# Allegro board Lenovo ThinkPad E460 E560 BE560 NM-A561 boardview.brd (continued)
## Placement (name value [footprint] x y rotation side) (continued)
RC435  10K_0402_5%  [R_0402]  119.17 97.07 0 top
RD1  1.8K_0402_1%  [R_0402]  58.98 36.69 90 top
RD2  2_0402_1%  [R_0402]  58.86 39.49 270 top
RD3  1.8K_0402_1%  [R_0402]  59.87 37.6 270 top
RD4  24.9_0402_1%  [R_0402]  57.08 38.57 90 top
RD9  1.8K_0402_1%  [R_0402]  101.53 24.73 90 top
RD10  2_0402_1%  [R_0402]  103.31 25.64 270 top
RD11  1.8K_0402_1%  [R_0402]  102.42 25.64 270 top
RD12  24.9_0402_1%  [R_0402]  105.09 25.64 270 top
RD15  1.8K_0402_1%  [R_0402]  58.27 49.95 90 top
RD16  1.8K_0402_1%  [R_0402]  59.15 50.86 270 top
RD17  2_0402_1%  [R_0402]  58.27 52.67 270 top
RD18  24.9_0402_1%  [R_0402]  56.5 51.75 90 top
RD19  10K_0402_5%  [R_0402]  121.6 48.48 90 top
RD21  470_0402_5%  [R_0402]  67.11 25.06 180 top
RD23  100K_0402_5%  [R_0402]  111.31 21.38 180 top
RD24  10K_0402_5%  [R_0402]  108.26 20.49 0 top
RD25  100K_0402_5%  [R_0402]  110.42 20.49 0 top
RE1  43_0402_5%  [R_0402]  197.92 38.83 90 top
RE2  10K_0402_5%  [R_0402]  201.29 61.13 90 top
RE3  100K_0402_1%  [R_0402]  183.2 55.62 180 top
RE4  100K_0402_5%  [R_0402]  207.17 51.42 270 top
RE5  4.7K_0402_5%  [R_0402]  183.19 49.39 180 top
RE6  4.7K_0402_5%  [R_0402]  183.2 46.47 180 top
RE7  18K_0402_1%  [R_0402]  183.2 56.51 180 top
RE8  10K_0402_5%  [R_0402]  203.88 57.27 0 top
RE9  10K_0402_5%  [R_0402]  208.21 133.44 180 top
RE15  100K_0402_5%  [R_0402]  204.92 51.04 180 top
RE31  10K_0402_5%  [R_0402]  188.78 40.83 270 top
RE32  10K_0402_5%  [R_0402]  187.89 40.83 270 top
RE33  10K_0402_5%  [R_0402]  191.22 37.52 270 top
RE38  10_0402_5%  [R_0402]  204.92 49.52 180 top
RE39  10K_0402_5%  [R_0402]  183.19 50.41 180 top
RE40  10K_0402_5%  [R_0402]  203 38.83 90 top
RE41  10K_0402_5%  [R_0402]  205.87 55.51 0 top
RE42  0_0402_5%  [R0402_SHORT]  204.12 55.51 0 top
RE43  0_0402_5%  [R0402_SHORT]  190.2 37.52 270 top
RE51  10K_0402_5%  [R_0402]  207.7 56.38 270 top
RE52  5.1K_0402_1%  [R_0402]  184.08 16.25 270 top
RE53  10K_0402_5%  [R_0402]  209.56 53.19 180 top
RG1  0_0402_5%  [R_0402]  198.33 65.04 0 top
RG4  100K_0402_5%  [R_0402]  197.21 70.98 270 top
RG5  10K_0402_5%  [R_0402]  206.3 72.1 90 top
RG6  10K_0402_5%  [R_0402]  204.27 72.1 90 top
RG7  0_0402_5%  [R_0402]  202.62 66.77 90 top
RG8  10K_0402_5%  [R_0402]  205.29 73.01 270 top
RL4  4.7K_0402_5%  [R_0402]  46.67 111.47 90 top
RL5  10K_0402_5%  [R_0402]  49.33 111.47 90 top
RL6  10K_0402_5%  [R_0402]  51.11 111.47 90 top
RL7  1K_0402_5%  [R_0402]  47.55 112.38 270 top
RL8  3.01K_0402_1%  [R_0402]  42.73 122.77 90 top
RL9  10K_0402_5%  [R_0402]  53.85 120.94 180 top
RL10  75_0805_5%  [R_0805]  22.54 124.14 0 bottom
RL11  75_0805_5%  [R_0805]  22.22 120.03 0 bottom
RL12  75_0805_5%  [R_0805]  22.7 114.52 0 bottom
RL13  75_0805_5%  [R_0805]  22.19 107.99 0 bottom
RL15  510_0402_1%  [R_0402]  18.34 124.2 270 bottom
RL16  510_0402_1%  [R_0402]  18.73 110.45 90 bottom
RL17  0_0402_5%  [R_0402]  53.85 120.05 180 top
RL18  0_0402_5%  [R0402_SHORT]  53.85 119.19 180 top
RL19  0_0603_5%  [R_0603]  60.88 122.59 180 top
RL20  0_0603_5%  [R0603_SHORT]  32 98.34 180 top
RL22  47K_0402_5%  [R_0402]  59.67 117.54 180 top
RL23  100K_0402_5%  [R_0402]  57.26 115.84 0 top
RL24  10K_0402_5%  [R_0402]  58.76 118.43 0 top
RL25  0_0402_5%  [R_0402]  58.17 114.95 180 top
RPC2  33_0804_8P4R_5%  [RP_0804_8P4R]  103.76 64.95 180 top
RPC9  10K_0804_8P4R_5%  [RP_0804_8P4R]  149.16 92.69 0 top
RPC15  10K_0804_8P4R_5%  [RP_0804_8P4R]  111.44 116.49 180 bottom
RPC18  10K_0804_8P4R_5%  [RP_0804_8P4R]  110.67 62.65 90 top
RPC22  10K_0804_8P4R_5%  [RP_0804_8P4R]  115.23 63.48 270 top
RPC23  33_0804_8P4R_5%  [RP_0804_8P4R]  124.53 121.01 270 bottom
RPC24  33_0804_8P4R_5%  [RP_0804_8P4R]  129.58 115.29 90 bottom
RPC200  10K_0804_8P4R_5%  [RP_0804_8P4R]  129.13 73.33 180 top
RPE1  10K_0804_8P4R_5%  [RP_0804_8P4R]  207.82 61.09 270 top
RPE2  10K_0804_8P4R_5%  [RP_0804_8P4R]  199.69 62.46 270 top
RPE3  10K_0804_8P4R_5%  [RP_0804_8P4R]  174.87 64.92 0 top
RPE4  100K_0804_8P4R_5%  [RP_0804_8P4R]  210.71 61.09 270 top
RPE5  2.2K_0804_8P4R_5%  [RP_0804_8P4R]  195.14 38.48 90 top
RT13  2.2K_0402_5%  [R_0402]  11.79 88.81 0 bottom
RT14  2.2K_0402_5%  [R_0402]  14.53 92.95 270 top
RT20  0_0402_5%  [R0402_SHORT]  13.68 88.59 270 top
RT21  75_0402_1%  [R_0402]  16.44 79.34 90 top
RT22  75_0402_1%  [R_0402]  16.44 81.62 90 top
RT23  75_0402_1%  [R_0402]  16.44 83.91 90 top
RT27  0_0402_5%  [R0402_SHORT]  16.69 92.18 270 top
RT28  0_0402_5%  [R0402_SHORT]  15.42 92.95 270 top
RT29  0_0402_5%  [R0402_SHORT]  11.79 87.92 0 bottom
RT34  0_0402_5%  [R0402_SHORT]  18.8 89.7 180 top
RT35  0_0402_5%  [R0402_SHORT]  19.46 94.43 180 top
RT36  2.2K_0402_5%  [R_0402]  24.69 94.43 270 top
RT37  2.2K_0402_5%  [R_0402]  12.71 87.03 180 bottom
RV4  0_0402_5%  [R_0402]  139.5 130.42 90 top
RV5  0_0402_5%  [R_0402]  138.61 130.42 90 top
RV6  1.69K_0402_1%  [R_0402]  144.53 140.91 180 top
RV7  1K_0402_5%  [R_0402]  151.69 151.58 180 top
RV8  1K_0402_5%  [R_0402]  142.77 140.2 90 top
RV9  10K_0402_5%  [R_0402]  129.57 94.43 180 bottom
RV10  1M_0402_5%  [R_0402]  165.74 131.1 180 bottom
RV11  10K_0402_5%  [R_0402]  152.91 116.47 0 top
RV13  10K_0402_5%  [R_0402]  153.83 118.25 180 top
RV14  10K_0402_5%  [R_0402]  152.01 116.7 270 top
RV15  10K_0402_5%  [R_0402]  156.39 112.56 180 top
RV16  0_0402_5%  [R_0402]  155.53 117.24 0 top
RV17  150_0402_1%  [R_0402]  158.93 129.63 90 bottom
RV18  40.2_0402_1%  [R_0402]  129.42 129.73 90 bottom
RV19  40.2_0402_1%  [R_0402]  133 129.73 90 bottom
RV20  100_0402_5%  [R_0402]  128.53 130.65 270 bottom
RV21  100_0402_5%  [R_0402]  134.83 130.65 270 bottom
RV22  40.2_0402_1%  [R_0402]  132.06 129.73 90 bottom
RV23  40.2_0402_1%  [R_0402]  135.72 129.76 90 bottom
RV24  100_0402_5%  [R_0402]  131.17 130.65 270 bottom
RV25  100_0402_5%  [R_0402]  136.61 130.67 270 bottom
RV26  243_0402_1%  [R_0402]  138.21 144.54 180 top
RV27  49.9_0402_1%  [R_0402]  167.32 154.62 180 bottom
RV28  10_0402_5%  [R_0402]  165.54 154.62 180 bottom
RV29  5.1K_0402_5%  [R_0402]  164.67 155.51 0 bottom
RV30  2.1K_0402_1%  [R_0402]  118.03 139.45 270 bottom
RV31  2.1K_0402_1%  [R_0402]  110.03 129.62 0 bottom
RV32  4.99K_0402_1%  [R_0402]  116.28 138.54 90 bottom
RV33  4.99K_0402_1%  [R_0402]  111.94 129.62 0 bottom
RV41  60.4_0402_1%  [R_0402]  115.06 137.63 0 top
RV42  60.4_0402_1%  [R_0402]  115.98 138.51 180 top
RV43  2.1K_0402_1%  [R_0402]  118.3 164.54 270 bottom
RV44  2.1K_0402_1%  [R_0402]  110.74 151.34 0 bottom
RV45  4.99K_0402_1%  [R_0402]  117.41 163.62 90 bottom
RV46  4.99K_0402_1%  [R_0402]  112.52 151.34 0 bottom
RV53  60.4_0402_1%  [R_0402]  115.01 160.13 0 top
RV54  60.4_0402_1%  [R_0402]  115.9 159.24 180 top
RV55  2.1K_0402_1%  [R_0402]  134.09 170.17 180 bottom
RV56  2.1K_0402_1%  [R_0402]  124.26 178.17 270 bottom
RV57  4.99K_0402_1%  [R_0402]  133.18 171.03 0 bottom
RV58  4.99K_0402_1%  [R_0402]  124.26 176.27 270 bottom
RV66  60.4_0402_1%  [R_0402]  133.15 173.14 270 top
RV67  60.4_0402_1%  [R_0402]  132.26 172.25 90 top
RV68  2.1K_0402_1%  [R_0402]  156.06 170.19 180 bottom
RV69  2.1K_0402_1%  [R_0402]  146.36 177.46 270 bottom
RV70  4.99K_0402_1%  [R_0402]  155.15 171.08 0 bottom
RV71  4.99K_0402_1%  [R_0402]  146.36 175.68 270 bottom
RV78  60.4_0402_1%  [R_0402]  155.15 173.14 270 top
RV79  60.4_0402_1%  [R_0402]  154.26 172.25 90 top
RV91  10K_0402_5%  [R_0402]  161.91 155.74 0 top
RV92  10K_0402_5%  [R_0402]  172.22 156.63 180 top
RV93  5.11K_0402_1%  [R_0402]  161.93 130.66 180 bottom
RV94  1K_0402_5%  [R_0402]  161.02 129.77 0 bottom
RV96  33_0402_5%  [R_0402]  166.12 156.83 90 top
RV97  33_0402_5%  [R_0402]  167.24 159.12 0 top
RV98  45.3K_0402_1%  [R_0402]  162.38 142.84 270 top
RV99  45.3K_0402_1%  [R_0402]  163.33 142.38 270 top
RV101  0_0402_5%  [R_0402]  161.5 148.27 180 top
RV102  47K_0402_5%  [R_0402]  163.76 127.85 90 top
RV103  10K_0402_5%  [R_0402]  163.76 129.76 90 top
RV104  47K_0402_5%  [R_0402]  164.65 130.67 270 top
RV105  2.2K_0402_5%  [R_0402]  164.65 128.77 270 top
RV106  8.45K_0402_1%  [R_0402]  158.04 129.63 90 bottom
RV107  10K_0402_1%  [R_0402]  159.49 129.83 0 top
RV108  4.99K_0402_1%  [R_0402]  151.69 141.77 180 top
RV109  4.75K_0402_1%  [R_0402]  157.16 130.55 270 bottom
RV110  0_0402_5%  [R_0402]  172.01 129.25 180 top
RV111  4.75K_0402_1%  [R_0402]  150.81 140.88 0 top
RV112  8.45K_0402_1%  [R_0402]  162.19 129.2 180 top
RV113  2K_0402_1%  [R_0402]  161.27 130.09 0 top
RV114  3.4K_0402_1%  [R_0402]  159.44 127.34 90 top
RV117  2.2K_0402_5%  [R_0402]  161.78 150.15 270 top
RV118  10K_0402_5%  [R_0402]  163.76 126.86 270 top
RV127  10K_0402_5%  [R_0402]  163.2 156.76 180 top
RV128  499_0402_1%  [R_0402]  150.78 152.44 0 top
RV129  0_0402_5%  [R_0402]  163.38 154.4 180 bottom
RV130  100_0402_5%  [R_0402]  163.38 155.28 180 bottom
RV131  10K_0402_5%  [R_0402]  164.5 148.22 180 top
RV132  10K_0402_5%  [R_0402]  161.45 146.14 180 top
RV133  10K_0402_5%  [R_0402]  162.82 153.07 180 top
RV134  10K_0402_5%  [R_0402]  168.89 154.34 0 top
RV135  10K_0402_5%  [R_0402]  161.37 147.03 180 top
RV136  10K_0402_5%  [R_0402]  161.45 145.23 180 top
RV137  10K_0402_5%  [R_0402]  150.6 144.54 0 top
RV138  10K_0402_5%  [R_0402]  160.58 150.15 270 top
RV139  10K_0402_5%  [R_0402]  161.47 152.01 270 top
RV140  10K_0402_5%  [R_0402]  160.58 152.01 270 top
RV142  0_0402_5%  [R_0402]  164.24 141.46 90 top
RV143  300_0402_5%  [R_0402]  182.17 131.18 270 top
RV144  0_0402_5%  [R_0402]  161.4 142.94 90 top
RV145  10K_0402_5%  [R_0402]  146.69 131.03 270 bottom
RV146  10K_0402_5%  [R_0402]  147.61 131.03 270 bottom
RV147  10K_0402_5%  [R_0402]  159.06 128.26 270 bottom
RV148  499_0402_1%  [R_0402]  149 131 270 bottom
RV149  0_0402_5%  [R_0402]  162.67 150.15 270 top
RV150  10K_0402_5%  [R_0402]  186.32 131.76 180 top
RV151  100K_0402_5%  [R_0402]  193.05 130.09 180 top
RV152  10K_0402_5%  [R_0402]  187.76 126.71 90 top
RV153  22K_0402_5%  [R_0402]  175.32 178.6 180 top
RV160  249_0402_1%  [R_0402]  150.35 154.29 270 top
RV161  47K_0402_5%  [R_0402]  176.59 122.01 90 top
RV162  470_0402_5%  [R_0402]  165.54 124.63 180 top
RV163  10K_0402_5%  [R_0402]  175.7 122.93 270 top
RV164  10K_0402_5%  [R_0402]  176.59 124.17 90 top
RV166  100K_0402_5%  [R_0402]  178.62 122.42 270 top
RV167  100K_0402_5%  [R_0402]  128.68 93.49 0 bottom
RV178  0_0402_5%  [R_0402]  161.91 154.85 0 top
RV179  0_0402_5%  [R_0402]  161.91 153.96 0 top
RV180  0_0402_5%  [R_0402]  166.1 159.55 270 top
RV181  0_0402_5%  [R_0402]  169.81 156.63 180 top
RV183  0_0402_5%  [R_0402]  179.63 121.5 90 top
RV185  0_0402_5%  [R_0402]  186.87 127.62 270 top
RV188  100K_0402_5%  [R_0402]  176.21 178.6 90 top
RV194  121_0402_1%  [R_0402]  116.46 137.5 270 bottom
RV195  1K_0402_1%  [R_0402]  103.64 140.3 90 top
RV197  1K_0402_1%  [R_0402]  111.03 139.44 90 top
RV198  121_0402_1%  [R_0402]  116.36 156.3 270 bottom
RV199  1K_0402_1%  [R_0402]  102.31 160.36 90 top
RV200  1K_0402_1%  [R_0402]  110.14 159.6 90 top
RV201  121_0402_1%  [R_0402]  132.14 171.74 180 bottom
RV202  1K_0402_1%  [R_0402]  133.38 185.84 0 top
RV203  1K_0402_1%  [R_0402]  132.62 177.99 0 top
RV204  121_0402_1%  [R_0402]  154.14 171.74 180 bottom
RV205  1K_0402_1%  [R_0402]  154.64 177.84 0 top
RV206  1K_0402_1%  [R_0402]  155.38 185.84 0 top
RV207  0_0402_5%  [R_0402]  127.69 94.45 270 bottom
RV208  10K_0402_5%  [R_0402]  168.15 181.01 180 top
RV209  100K_0402_5%  [R_0402]  163.89 178.27 90 top
RV210  0_0402_5%  [R_0402]  164.76 178.28 0 top
RVG16  1M_0402_5%  [R_0402]  25.53 84.32 0 top
RVG18  36_0402_5%  [R_0402]  23.55 88.43 180 top
RVG19  36_0402_5%  [R_0402]  23.55 89.32 180 top
RVG129  0_0402_5%  [R0402_SHORT]  29.17 94.4 270 top
RVG130  0_0805_5%  [R0805_SHORT]  37.65 86.81 270 top
RVG131  1.2K_0402_1%  [R_0402]  22.87 86.2 0 top
RVG132  10K_0402_5%  [R_0402]  27.36 94.4 270 top
RVG133  10K_0402_5%  [R_0402]  26.47 94.4 270 top
RVG134  10K_0402_5%  [R_0402]  28.25 93.51 90 top
RVG135  10K_0402_5%  [R_0402]  25.58 93.51 90 top
RW3  0_0603_5%  [R0603_SHORT]  41.64 32.76 270 top
RW4  0_0402_5%  [R0402_SHORT]  48.65 29.38 180 bottom
RW8  6.2K_0402_1%  [R_0402]  44.56 33.9 0 top
RW11  10K_0402_5%  [R_0402]  55.05 29.81 180 top
RW12  100K_0402_5%  [R_0402]  55.96 29.81 90 top
RW13  100K_0402_5%  [R_0402]  55.96 32.53 270 top
RW14  0_0402_5%  [R0402_SHORT]  54.16 31.64 0 top
RW15  0_0402_5%  [R0402_SHORT]  54.16 30.7 0 top
RW16  10_0402_5%  [R_0402]  27.29 33.69 0 bottom
RW18  0_0402_5%  [R0402_SHORT]  53.27 26.84 270 top
RW20  10K_0402_5%  [R_0402]  55.05 32.55 180 top
RW21  0_0402_5%  [R0402_SHORT]  49.54 28.49 180 bottom
RW22  0_0402_5%  [R0402_SHORT]  49.54 27.6 180 bottom
RW23  0_0402_5%  [R0402_SHORT]  50.48 25.95 90 top
RW24  0_0402_5%  [R0402_SHORT]  51.36 25.95 90 top
RW25  0_0402_5%  [R0402_SHORT]  52.25 25.95 90 top
RX1  0_0805_5%  [R0805_SHORT]  19.36 71.5 270 top
RX2  4.99K_0402_1%  [R_0402]  17.38 59.22 0 top
RX3  4.7K_0402_5%  [R_0402]  24.28 69.55 270 top
RX4  4.7K_0402_5%  [R_0402]  24.47 70.52 90 top
RX5  4.7K_0402_5%  [R_0402]  19.56 63.41 180 bottom
RX6  4.7K_0402_5%  [R_0402]  21.98 63.41 180 bottom
RX7  4.7K_0402_5%  [R_0402]  19.56 62.14 180 bottom
RX8  4.7K_0402_5%  [R_0402]  21.98 62.14 180 bottom
RX9  4.7K_0402_5%  [R_0402]  28.78 69.55 270 top
RX10  4.7K_0402_5%  [R_0402]  30.05 64.93 0 top
RX11  4.7K_0402_5%  [R_0402]  30.05 65.83 0 top
RX12  4.7K_0402_5%  [R_0402]  29.67 68.64 90 top
RX13  4.7K_0402_5%  [R_0402]  24.03 57.28 270 top
RX14  4.7K_0402_5%  [R_0402]  24.92 56.37 90 top
RX15  4.7K_0402_5%  [R_0402]  30.89 58.33 180 top
RX16  4.7K_0402_5%  [R_0402]  29.98 57.44 0 top
RX17  4.7K_0402_5%  [R_0402]  30.87 59.22 180 top
RX18  4.7K_0402_5%  [R_0402]  29.95 60.11 0 top
RX19  4.7K_0402_5%  [R_0402]  21.01 56.35 90 top
RX20  4.7K_0402_5%  [R_0402]  21.9 57.27 270 top
RX21  1M_0402_5%  [R_0402]  28.5 57.27 270 top
SW1  NTC010-AK1G-B160T_4P  [SW_NTC010-AK1G-B160T_4P]  223.95 124.38 90 bottom
T21  PAD  [TPC12]  100.64 89.7 0 top
T23  PAD  [TPC12]  48.44 110.53 90 top
T24  PAD  [TPC12]  50.22 112.16 90 top
T25  PAD  [TPC12]  8.69 85.84 0 top
T26  PAD  [TPC12]  10.09 94.27 0 top
T56  PAD  [TPC12]  112.53 69.71 0 top
T57  PAD  [TPC12]  114.33 66.33 0 top
T59  PAD  [TPC12]  66.94 113.88 180 bottom
T96  PAD  [TPC12]  221.21 155.97 0 top
TC1  PAD  [TPC12]  81.84 117.51 0 top
TC2  PAD  [TPC12]  78.54 110.02 180 bottom
TC7  PAD  [TPC12]  80.83 116.35 0 top
TC9  PAD  [TPC12]  79.58 111.32 180 bottom
TC10  PAD  [TPC12]  80.02 115.31 0 top
TC16  PAD  [TPC12]  84.18 101.54 0 top
TC17  PAD  [TPC12]  85.2 102.71 0 top
TC18  PAD  [TPC12]  106.86 67.73 0 top
TC20  PAD  [TPC12]  121.72 69.64 0 top
TC21  PAD  [TPC12]  101.91 89.75 0 top
TC24  PAD  [TPC12]  123.3 69.25 0 top
TC25  PAD  [TPC12]  78.16 113.51 180 bottom
TC26  PAD  [TPC12]  71.88 112.75 0 top
TC27  PAD  [TPC12]  123.32 100.01 0 top
TC30  PAD  [TPC12]  67.24 109.54 180 bottom
TC31  PAD  [TPC12]  53.32 83.35 180 bottom
TC32  PAD  [TPC12]  54.69 83.35 180 bottom
TC33  PAD  [TPC12]  66.73 108.37 180 bottom
TC34  PAD  [TPC12]  66.78 109.08 0 top
TC35  PAD  [TPC12]  65.21 109.07 0 top
TC36  PAD  [TPC12]  64.32 114.09 0 top
TC37  PAD  [TPC12]  124.57 87.85 180 bottom
TC38  PAD  [TPC12]  124.29 86.53 180 bottom
TC39  PAD  [TPC12]  57.99 109.36 180 bottom
TC40  PAD  [TPC12]  56.01 109.26 180 bottom
TC41  PAD  [TPC12]  62.16 109.49 0 top
TC42  PAD  [TPC12]  58.86 110.4 180 bottom
TC43  PAD  [TPC12]  66.83 112.43 180 bottom
TC44  PAD  [TPC12]  68 108.24 180 bottom
TC45  PAD  [TPC12]  102.5 88.69 0 top
TC46  PAD  [TPC12]  104.32 88.69 0 top
TC47  PAD  [TPC12]  65.14 110.4 0 top
TC48  PAD  [TPC12]  60.51 110.66 180 bottom
TC49  PAD  [TPC12]  54.24 110.38 180 bottom
TC50  PAD  [TPC12]  122.26 77.31 0 top
TC51  PAD  [TPC12]  120.78 77.21 0 top
TC52  PAD  [TPC12]  62.29 110.99 0 top
TC53  PAD  [TPC12]  110.67 110.1 0 top
TC54  PAD  [TPC12]  57 110.28 180 bottom
TC55  PAD  [TPC12]  111.54 109.11 0 top
TC56  PAD  [TPC12]  114.56 110.5 180 bottom
TC57  PAD  [TPC12]  64.51 112.43 0 top
TC58  PAD  [TPC12]  114.61 111.8 180 bottom
TC59  PAD  [TPC12]  71.94 111.48 0 top
TC60  PAD  [TPC12]  114 109.31 180 bottom
TC61  PAD  [TPC12]  63.62 115.36 0 top
TC62  PAD  [TPC12]  114.1 108.04 180 bottom
TC63  PAD  [TPC12]  62.29 115.29 0 top
TC64  PAD  [TPC12]  123.15 90.31 180 bottom
TC65  PAD  [TPC12]  116.95 109.31 180 bottom
TC66  PAD  [TPC12]  115.42 107.91 180 bottom
TC67  PAD  [TPC12]  122.99 87.49 180 bottom
TC68  PAD  [TPC12]  127.74 86.04 180 bottom
TC69  PAD  [TPC12]  123.12 88.81 180 bottom
TC70  PAD  [TPC12]  126.37 86.04 180 bottom
TC71  PAD  [TPC12]  115.65 109.41 180 bottom
TC72  PAD  [TPC12]  112.63 108.85 180 bottom
TC73  PAD  [TPC12]  115.7 111.09 180 bottom
TC74  PAD  [TPC12]  113.24 110.35 180 bottom
TC75  PAD  [TPC12]  83.06 101.87 0 top
TC76  PAD  [TPC12]  115.14 70.93 0 top
TC77  PAD  [TPC12]  82.43 100.19 0 top
TC78  PAD  [TPC12]  64.57 110.53 180 bottom
TC79  PAD  [TPC12]  114.31 69.59 0 top
TC80  PAD  [TPC12]  65.08 109.26 180 bottom
TC81  PAD  [TPC12]  112.43 67.98 0 top
TC82  PAD  [TPC12]  63.56 109.64 180 bottom
TC83  PAD  [TPC12]  52.69 110.33 180 bottom
TC84  PAD  [TPC12]  53.45 109.29 180 bottom
TC85  PAD  [TPC12]  62.62 110.61 180 bottom
TC86  Test_Point_40MIL  [TPC40]  73.84 109.36 0 top
TC87  PAD  [TPC12]  79.61 116.75 0 top
TC88  PAD  [TPC12]  79.94 110.05 180 bottom
TC89  PAD  [TPC12]  78.03 116.31 0 top
TC91  PAD  [TPC12]  127.46 87.75 180 bottom
TC93  PAD  [TPC12]  125.91 87.57 180 bottom
TC94  PAD  [TPC12]  62.29 114.02 0 top
TC95  PAD  [TPC12]  62.31 112.38 0 top
TC96  Test_Point_40MIL  [TPC40]  77.5 88.94 0 top
TC97  PAD  [TPC12]  61.02 77.51 0 top
TC98  PAD  [TPC12]  61.02 75.86 0 top
TC99  PAD  [TPC12]  68.69 109.23 0 top
TC100  Test_Point_40MIL  [TPC40]  79.53 88.53 0 top
TC102  PAD  [TPC12]  64.32 77.64 0 top
TC103  PAD  [TPC12]  62.67 77.64 0 top
TC104  PAD  [TPC12]  113.82 112.03 0 top
TC105  PAD  [TPC12]  114.76 110.4 0 top
TC106  PAD  [TPC12]  65.97 77.64 0 top
TC107  PAD  [TPC12]  108.01 120.69 180 bottom
TC108  PAD  [TPC12]  66.1 75.86 0 top
TC109  PAD  [TPC12]  106.61 120.69 180 bottom
TC110  PAD  [TPC12]  111.08 109.46 180 bottom
TC111  PAD  [TPC12]  108.01 122.09 180 bottom
TC112  PAD  [TPC12]  124.39 91.99 180 bottom
TC113  PAD  [TPC12]  106.74 118.3 180 bottom
TC114  PAD  [TPC12]  127.49 91.38 180 bottom
TC115  PAD  [TPC12]  106.13 116.96 180 bottom
TC116  PAD  [TPC12]  113.82 109.46 0 top
TC117  PAD  [TPC12]  81.36 102.94 0 top
TC118  PAD  [TPC12]  101.56 87.34 0 top
TC119  PAD  [TPC12]  72.24 109.82 180 bottom
TC120  PAD  [TPC12]  103.31 85.32 0 top
TC121  PAD  [TPC12]  126.42 73.32 0 top
TG1  PAD  [TPC12]  203.09 72.46 0 top
TL1  BOTHHAND_NA69LF  [TAIMA_IH-189-A_24P]  36.9 123.74 270 bottom
TP92  Test_Point_40MIL  [TPC40]  62.67 75.86 0 top
TP93  Test_Point_40MIL  [TPC40]  64.32 75.86 0 top
TP120  Test_Point_40MIL  [TPC40]  112.05 120.16 0 bottom
TP121  Test_Point_40MIL  [TPC40]  116.49 125.11 0 bottom
TP124  Test_Point_40MIL  [TPC40]  120.91 120.77 0 bottom
TP125  Test_Point_40MIL  [TPC40]  164.98 56.22 0 top
TP126  Test_Point_40MIL  [TPC40]  171.15 51.02 0 top
TP127  Test_Point_40MIL  [TPC40]  178.24 51.07 0 top
TP128  Test_Point_40MIL  [TPC40]  178.36 53.7 0 top
TP129  Test_Point_40MIL  [TPC40]  119.82 64.63 0 top
TP939  Test_Point_40MIL  [TPC40]  31.6 61.61 0 top
TP940  Test_Point_40MIL  [TPC40]  114.51 125.34 0 bottom
TP941  Test_Point_40MIL  [TPC40]  133.15 78.21 0 top
TP942  Test_Point_40MIL  [TPC40]  131.63 78.21 0 top
TPV1  Test_Point_32MIL  [TPC32]  167.21 157.72 0 top
TPV3  Test_Point_20MIL  [TPC20]  159.19 156.99 0 top
TPV4  Test_Point_20MIL  [TPC20]  159.29 153.89 0 top
TPV5  Test_Point_20MIL  [TPC20]  159.26 151.22 0 top
TPV6  Test_Point_20MIL  [TPC20]  160.53 156.91 0 top
TPV7  Test_Point_20MIL  [TPC20]  159.19 147.74 0 top
TPV8  Test_Point_20MIL  [TPC20]  163.4 147.18 0 top
TPV9  Test_Point_20MIL  [TPC20]  150.96 145.51 0 top
TPV10  Test_Point_20MIL  [TPC20]  159.37 145.12 0 top
TPV11  Test_Point_20MIL  [TPC20]  160.23 144.11 0 top
TPV12  Test_Point_20MIL  [TPC20]  162.54 148.25 0 top
TPV13  Test_Point_20MIL  [TPC20]  159.62 142.56 0 top
TPV14  Test_Point_20MIL  [TPC20]  151.14 143.09 0 top
TPV15  Test_Point_20MIL  [TPC20]  159.29 152.57 0 top
TPV16  Test_Point_20MIL  [TPC20]  145.07 138.72 0 top
TPV17  Test_Point_20MIL  [TPC20]  159.31 146.42 0 top
TPV18  Test_Point_20MIL  [TPC20]  160.71 139 0 top
TPV20  Test_Point_20MIL  [TPC20]  162.11 139 0 top
TPV21  Test_Point_20MIL  [TPC20]  163.43 138.98 0 top
TPV22  Test_Point_20MIL  [TPC20]  159.16 149.16 0 top
U1  -  [F75303M_MSOP10]  118.19 179.82 180 bottom
U3  -  [G524B1T11U_SOT23-5]  91.24 134.95 225 bottom
U4  -  [G5243AT11U_SOT23-5]  95.06 139.23 135 bottom
U7  -  [G524B1T11U_SOT23-5]  188.5 15.6 90 top
U11  -  [TPS22966DPUR_WSON14_2X3]  185.47 25.75 270 top
U15  -  [G524B2T11U_SOT23-5]  25.58 24.76 270 top
U148  SIP32451DB-T2-GE1_WCSP4  [SIP32451DB-T2-GE1_WCSP_4P]  125.73 65.12 180 top
U149  -  [SLG5NT1533VTR_STDFN8-6_1X1P6]  129.94 66.33 270 top
U150  -  [G5243AT11U_SOT23-5]  222.35 46.46 180 bottom
UA1  -  [CX11852-11Z_QFN40_5X5]  210.98 23.24 270 top
UC1  SKYLAKE-U_BGA1356  [SKYLAKE-U_BGA_1356P-T]  109.68 104.96 0 bottom
UC3  -  [TC7SG17FE_SON5]  49.98 108.02 90 top
UC4M1  -  [W25Q32FVSSIQ_SO8]  227.23 24.65 180 top
UC8M2  W25Q64FVSSIQ_SO8  [ACES_91960-0084N_8P]  135.03 118.45 0 bottom
UE1  -  [IT8586E-AX_LQFP128_14X14]  201.34 44.47 90 top
UGSEN1  LIS3DHTR_LGA16_3x3  [LIS3DHTR_LGA16_3X3]  207.01 66.94 180 top
UL1  -  [WGI219LM-QREF-A0_QFN48_6X6]  49.91 120.55 180 top
UNK46J BARCODE  -  []  44.63 88.81 180 bottom
USROM1  -  [PCA24S08AD_SO8]  86.55 132.35 270 bottom
UT3  SN74AHCT1G125DCKR_SC70-5  [NC7SZ04P5X_NL_SC70-5]  17 87.24 90 top
UT4  SN74AHCT1G125DCKR_SC70-5  [NC7SZ04P5X_NL_SC70-5]  20.02 91.97 90 top
UTPM1  -  [NPCT650LA0YX_QFN32_5X5]  114.92 122.63 270 bottom
UV1  216-0855000_A0_FCBGA962  [2160846033-A0_FCBGA_962P]  130.2 161.56 270 bottom
UV5  H5GC2H24BFR-T2C_BGA170  [H5GQ1H24AFR-T2L_BGA_170P]  103.51 153.58 0 bottom
UV6  H5GC2H24BFR-T2C_BGA170  [H5GQ1H24AFR-T2L_BGA_170P]  103.51 131.96 0 bottom
UV7  H5GC2H24BFR-T2C_BGA170  [H5GQ1H24AFR-T2L_BGA_170P]  126.6 184.69 270 bottom
UV8  H5GC2H24BFR-T2C_BGA170  [H5GQ1H24AFR-T2L_BGA_170P]  148.6 184.69 270 bottom
UV12  -  [TPS22965DSGR_WSON8_2X2]  173.41 173.9 270 top
UV14  -  [74AVCH2T45GD_XSON8_3X2]  164.09 154.94 270 top
UV15  -  [MC74VHC1G08DFT2G_SC70-5]  126.42 94.99 270 bottom
UVG2  -  [PTN3356R1BS_HVQFN32_5X5]  30.88 86.67 180 top
UW1  -  [RTS5227S-GRT_QFN32_4X4]  51.49 33.3 270 top
UX1  -  [PS8339BQFN56GTR2-A1_QFN56_7X7]  27.27 66.22 270 top
YC1  32.768KHZ_12.5PF_9H03200042  [Y_9H03200042_2P]  117.96 89.86 270 top
YC2  24MHZ_10PF_8Y24000011  [Y_8Y24000011_4P]  90.16 119.63 180 bottom
YL1  25MHZ_10PF_8Y25000010  [Y_8Y25000010_4P]  46.35 126.32 180 top
YV1  27MHZ_16PF_7V27000011  [Y_X3G027000FG1H-HX_4P]  168.03 127.84 180 bottom
YVG1  27MHZ_10PF_7V27000050  [Y_7V25000014_4P]  23.81 80.15 0 top

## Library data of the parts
AOU1 = TPS2546RTER_QFN16_4X4
C1-C5 C8-C29 C50-C52 C69-C75 C115 C116 C119 C121 C123 C124 C129-C132 C164 C165 C171 C172 C202-C205 C750 C751 C8496-C8499 C8528-C8530 C8532-C8534 C8536 C8537 C8540 C8542-C8545 CA1-CA19 CA22-CA32 CA40 CA42 CA43 CC1-CC7 CC9 CC18-CC26 CC46 CC47 CC49 CC50 CC52 CC58-CC61 CC68-CC70 CC86-CC97 CC99 CC102 CC106-CC109 CC142-CC161 CC170-CC179 CC190-CC209 CC231 CC233-CC235 CC249-CC264 CC271-CC274 CD1-CD3 CD8-CD21 CD23-CD26 CD29-CD33 CD38-CD49 CD51-CD60 CE1-CE17 CG1-CG6 CL1-CL13 CL17 CRF1-CRF18 CRF21 CRF22 CT24-CT29 CT31 CV1-CV8 CV17-CV80 CV83-CV88 CV96-CV100 CV106 CV107 CV111-CV134 CV137-CV142 CV150-CV154 CV160 CV161 CV163 CV165-CV170 CV177-CV181 CV187 CV205-CV229 CV232 CV233 CV236-CV241 CVG15-CVG20 CVG34-CVG44 CW1-CW14 CX2-CX16 PC1 PC2 PC108 PC111 PC112 PC208 PC212 PC225 PC229-PC231 PC305 PC316 PC401 PC403 PC409 PC417 PC427 PC438 PC440 PC452 PC461 PC602 PC609 PC617 PC620 PC623 PC634 PC714 = CAP NP
C44 C45 = CAP NP: room: TRACK
C122 C8531 CD22 = CAP WP
C747 C749 C8541 CC104 CC105 CC123 CC129-CC131 CC133 CC136-CC141 CC218 CC221-CC230 CC232 CC236 CC237 CC239 CC241 CC244 CC245 CC247 CVG32 CVG33 PC3-PC10 PC102-PC107 PC109 PC110 PC115-PC120 PC122-PC124 PC128 PC201 PC203 PC210 PC211 PC213 PC215 PC217 PC218 PC223 PC224 PC227 PC228 PC301 PC304 PC307-PC310 PC312 PC313 PC315 PC318 PC319 PC402 PC404-PC408 PC410-PC416 PC418-PC426 PC428-PC431 PC436 PC437 PC439 PC441 PC442 PC444 PC450 PC451 PC453 PC455 PC459 PC460 PC462 PC463 PC604 PC605 PC608 PC610 PC612 PC618 PC619 PC621 PC622 PC628 PC633 PC635-PC637 PC701-PC710 PC716 PC717 PC801-PC803 PC805-PC808 RC381-RC383 RC386 = P_CAP NP
D1 PD7 = PESD5V0U2BT_SOT23-3
D4 = AZC199-02SPR7G_SOT23-3
D5 = RB491D_SOT23-3
D6 DA5-DA7 DV4 DV5 DV7 = RB751V-40_SOD323-2
D7 D17 DT1 DT2 = CM1293A-04SO_SC-74-6
D8 D12-D14 D16 DL1 DL2 = RCLAMP0524PATCT_SLP2510P8-10-9
D11 D15 D59-D65 DC23 = RB521CS-30GT2RA_VMN2-2
DA1 = BAT54CW_SOT323-3
DEV1 PD1-PD4 PD6 PD101-PD103 PD801 = P_RB751V-40_SOD323-2
DL3-DL6 = LSE-200NX3216TRLF_1206-2
F2 = 0.5A_8V_KMC3S050RY
FD1-FD6 = FM_2
H1-H6 H8-H28 = HOLE
IT1-IT8 TC86 TC96 TC100 TP92 TP93 TP120 TP121 TP124-TP129 TP939-TP942 = Test_Point_40MIL
J1 = JOPEN: User Part Number: PART#; room: EC
J5 J6 JC5 JV1 PJ201-PJ204 PJ301-PJ304 PJ701-PJ703 PJ801 PJ802 = P_JUMP_43X118
JAUF = ACES_50506-01201-001
JBATT1 = P_SUYIN_1
JC1 = P_JUMP
JCMOS1 JME1 = JOPEN: User Part Number: PART#; room: PCH
JCP = ACES_50506-01201-AT1
JCRT = SUYIN_070546HR015S21BZR
JDCIN1 = ACES_50271-00701-001
JDIMM1 = LCN_DAN06-K4406-0102
JDIMM2 = LCN_DAN06-K4406-0103
JFAN = ACES_2
JFPB = ACES_88514-0060N-071
JHDD = ACES_50812-0227P-001
JHDMI = CONCR_099ATAC19NBLCNF
JKB = JAE_FL10F032HA2R3000
JLCD = I-PEX_1
JODD = ACES_50885-0137P-001
JREAD2 = SUYIN_250312HB011M106ZL
JRJ452 = FOX_JM3611-RS800013-7H
JRTC = TE_2041180-2
JSPK = TYCO_2041180-4
JTOUCH = ACES_50463-0104A-P01
JTP = JAE_FL10F012HA1R3000
JU3LC = ACES_50406-02071-001
JU3LF = HIGHS_FC5AF261-1151H
JUSB1 JUSB2 = TAITW_PUBAU1-09FNLSCNN4H0
JV4 = JUMP
JWLBT = TYCO_2
L1-L13 L15-L20 L22 = EXC24CH900U_4P
L21 LT1-LT3 LV3 LV6 PL1-PL4 PL401 PL402 PL404 PL405 PL407 PL601 PL602 PL801 RA8-RA10 RA12 = L
LC1-LC5 R64 R68 R70 R229-R231 R9460 R9474 R9475 RA1 RA4 RA27 RA28 RA30 RA32 RC11 RC21 RC40 RC41 RC109 RC121 RC124 RC126 RC132 RC142 RC173 RC176 RC183 RC185 RC197 RC293 RC295 RC296 RC304 RC310-RC317 RC326 RC330 RC333 RC341 RC373 RC380 RC411 RE42 RE43 RL18 RL20 RT20 RT27-RT29 RT34 RT35 RVG129 RVG130 RW3 RW18 RX1 = R-SHORT
LE1 LE2 LV4 LV5 = BLM18PG121SN1D_2P
LL1 = L: room: LAN
PC101 PC314 = CAP NP: room: ESATA
PC113 PC114 PC121 PC125-PC127 PC202 PC209 PC214 PC216 PC226 PC302 PC303 PC317 PC432-PC435 PC445-PC449 PC456-PC458 PC464 PC601 PC603 PC606 PC607 PC611 PC615 PC616 PC624-PC627 PC631 PC632 PC718 PC804 = P_CAP NP: room: CPU_CORE
PC204-PC207 PC219-PC222 PC711-PC713 PC715 = CAP NP: room: CPU
PC306 = P_CAP NP: room: DDR_VTT
PC311 PC443 PC454 PC525-PC529 PC613 PC614 PC629 PC630 = P_CAP WP
PC465-PC524 = CAP NP: room: KB
PD5 = AZ5425-01F_DFN1006P2E2
PF1 = 7A_32V_0437007.WR
PF2 = P_12A_65V_451012MRL
PL101 PL102 PL201 PL202 PL301 PL403 PL406 PL408 PL603 PL604 PL701 = P_L
PQ1 = P_MMBT3906_SOT23-3_0
PQ2 = P_MMBT3904_SOT23-3_0
PQ4 PQ201 = P_2N7002BKS_SOT363-6
PQ101 PQ102 PQ104 = P_SIS406DN-T1-GE3_PAK1212-8-5
PQ103 PQ105 Q5 QE1 QL3 QV1 QV17 = P_2N7002KW_SOT323-3
PQ106 PQ107 PQ301 PQ302 PQ407 PQ408 = P_AON7408L_DFN8-5_1
PQ401 PQ404 PQ601 PQ604 = P_TPCA8065-H_PPAK56-8-5_0
PQ402 PQ403 PQ405 PQ406 PQ602 PQ603 PQ605 PQ606 QV24 = P_TPCA8059-H_PPAK56-8-5_0
PR1-PR12 PR14 PR15 PR18 PR19 PR101 PR103-PR107 PR113-PR115 PR117 PR130-PR132 PR201 PR208 PR210 PR211 PR216 PR217 PR301 PR306 PR307 PR309 PR311 PR313 PR402 PR403 PR405 PR406 PR409-PR415 PR419 PR420 PR422 PR423 PR425 PR426 PR430-PR432 PR438-PR442 PR445-PR448 PR604 PR617 PR619 PR624 PR627-PR629 PR633 PR635 PR637 PR639 PR641-PR643 PR702 PR703 PR705 PR706 PR802 PR804 PR805 R9488 RC95 RC97 RC100 RC298 RC300-RC302 RC307 RC308 RC350 RC384 RC385 RV30 RV31 RV43 RV44 RV55 RV56 RV68 RV69 = P_R
PR13 PR109 PR118 PR120-PR124 PR126 PR129 PR202 PR203 PR205 PR212 PR213 PR310 PR312 PR407 PR408 PR417 PR435 PR451 PR452 PR455 PR456 PR459 PR460 PR601-PR603 PR605 PR606 PR609-PR612 PR614 PR615 PR620 PR621 PR625 PR701 PR707 PR801 = P_R-SHORT
PR16 PR308 PR421 = P_R: room: VSB
PR17 PR206 PR207 PR209 PR215 PR302 PR305 PR401 PR404 PR416 PR418 PR424 PR427-PR429 PR433 PR434 PR436 PR437 PR443 PR444 PR613 PR622 PR623 PR626 PR634 PR638 PR640 R2 R3 R17 R18 R21 R25 R26 R28 R51 R61 R66 R67 R69 R71 R89-R91 R105-R108 R111 R112 R151-R154 R156 R157 R159 R163-R178 R217 R224 R225 R233-R239 R484 R9449 R9472 R9473 R9476-R9487 R9489-R9493 RA2 RA3 RA5 RA11 RA13-RA25 RA29 RA31 RC1-RC6 RC8-RC10 RC12-RC14 RC16 RC19 RC20 RC24 RC26 RC27 RC29-RC32 RC34 RC47 RC48 RC52-RC56 RC67 RC70 RC71 RC74 RC83 RC86 RC88 RC92 RC93 RC98 RC99 RC101-RC105 RC108 RC117 RC118 RC120 RC123 RC125 RC127 RC143 RC144 RC151 RC152 RC159 RC165 RC166 RC184 RC189 RC192 RC200 RC201 RC204 RC209 RC277 RC286-RC288 RC294 RC297 RC299 RC306 RC344 RC348 RC351-RC356 RC372 RC374-RC376 RC378 RC379 RC387-RC390 RC392-RC403 RC406 RC407 RC409 RC410 RC413 RC426 RC433-RC435 RD1-RD4 RD9-RD12 RD15-RD19 RD21 RD24 RE1-RE9 RE15 RE31-RE33 RE38-RE41 RE51-RE53 RG1 RG4-RG8 RL4-RL9 RL15-RL17 RL19 RL22-RL25 RT13 RT14 RT21-RT23 RT36 RT37 RV6-RV11 RV13-RV29 RV32 RV33 RV41 RV42 RV45 RV46 RV53 RV54 RV57 RV58 RV66 RV67 RV70 RV71 RV78 RV79 RV91-RV94 RV96-RV99 RV101-RV114 RV117 RV118 RV127-RV140 RV142-RV153 RV160-RV164 RV166 RV167 RV178-RV181 RV183 RV185 RV188 RV208-RV210 RVG16 RVG18 RVG19 RVG131-RVG135 RW8 RW11-RW13 RW16 RW20 RX2 RX21 = R
PR102 PR111 PR112 PR125 PR128 = P_R: room: CHARGER
PR108 PR110 = P_R: room: CPUCOREP
PR116 PR119 PR204 PR214 PR303 PR304 PR449 PR450 PR453 PR454 PR457 PR458 PR607 PR608 PR616 PR618 PR630-PR632 PR636 PR704 PR708 PR803 RC391 = P_R: room: CPU_CORE
PRT1-PRT6 = 540_0402NEW_30%_PRF15BB541NB6RC
PRT7 = P_100K_0402_1%_NCP15WF104F03RC
PRT401-PRT405 = P_MURAT_NCP03WF104F05RL
PRT601 = P_MURAT_NCP18XH103D03RB
PRT602 = P_470K_0402NEW_3%_TH05-4K474HR
PU1 = P_G718TM1U_SOT23-8
PU101 = P_BQ24780RUYR_QFN24_3
PU201 = P_SYX198BQNC_QFN10_3X3
PU202 = P_SYX198CQNC_QFN10_3X3
PU301 = P_RT8231AGQW_WQFN20_2
PU401 = P_NCP81208MNTXG_QFN48_6X6
PU402 PU404 = P_NCP81253MNTBG_DFN8_1
PU403 = P_NCP81151MNTBG_DFN8_0
PU601 = P_ISL62771HRTZ_TQFN40_5
PU701 = P_TPS51367RVER_QFN28_3P5X4P5
PU801 = P_RT8068AZQW_WDFN10_1
Q1 Q2 QV4 = MMST3904-7-F_SOT323-3
Q6 Q24 QC1-QC3 QG2 QT1 QV5 QV18 QV19 QV23 = P_2N7002KDWH_SOT363-6
Q22 = AO3401A_SOT23-3
Q23 QV9 = AO4430L_SO8
Q26 Q27 QG1 QL2 QV6 = AO3413_SOT23-3
QD1 = DTC115TMT2L_VMT3
R59 R60 R63 R65 RC106 RC107 RX3-RX20 = R: room: TRACK
R150 RC427-RC432 RV4 RV5 RV207 = R: room: GPU
RC415 RC422-RC425 = R_0: room: CPU
RD23 RD25 = R: room: 46
RL10-RL13 = R: room: LAN
RPC2 RPC9 RPC15 RPC18 RPC22-RPC24 RPC200 RPE1-RPE5 = RP_8P4R
RV194 RV195 RV197-RV206 = R: room: VRAM1
RW4 RW14 RW15 RW21-RW25 = R-SHORT: signal model: R_R_0402_0_0402_5%_0_0402_5%
SW1 = NTC010-AK1G-B160T_4P
T21 T23-T26 T56 T57 T59 T96 TC1 TC2 TC7 TC9 TC10 TC16-TC18 TC20 TC21 TC24-TC27 TC30-TC85 TC87-TC89 TC91 TC93-TC95 TC97-TC99 TC102-TC121 TG1 = PAD_6: room: CPU
TL1 = TAIMA_IH-189-A
TPV1 = Test_Point_32MIL
TPV3-TPV18 TPV20-TPV22 = Test_Point_20MIL
U1 = F75303M_MSOP10
U3 U7 = G524B1T11U_SOT23-5
U4 U150 = G5243AT11U_SOT23-5
U11 = TPS22966DPUR_WSON14_2X3
U15 = G524B2T11U_SOT23-5
U148 = P_SIP32451DB-T2-GE1_WCSP4
U149 = P_SLG5NT1533VTR_STDFN8-6_1X1P6
UA1 = CX11852-11Z_QFN40_5X5
UC1 = SKYLAKE-U_BGA1356
UC3 = TC7SG17FE_SON5
UC4M1 = W25Q32FVSSIQ_SO8
UC8M2 = W25Q64FVSSIQ_SO8
UE1 = IT8586E-AX_LQFP128_14X14
UGSEN1 = LIS3DHTR_LGA16_3X3
UL1 = WGI219LM-QREF-A0_QFN48_6X6
USROM1 = PCA24S08AD_SO8
UT3 UT4 = SN74AHCT1G125DCKR_SC70-5: room: CRT
UTPM1 = NPCT650LA0YX_QFN32_5X5
UV1 = 2160846033-A0_FCBGA962
UV5-UV8 = H5GQ1H24AFR-T2L_BGA170_8: room: VRAM1
UV12 = TPS22965DSGR_WSON8_2X2
UV14 = 74AVCH2T45GD_XSON8_3X2
UV15 = MC74VHC1G08DFT2G_SC70-5
UVG2 = PTN3356R1BS_HVQFN32_5X5
UW1 = RTS5227S-GRT_QFN32_4X4
UX1 = PS8339BQFN56GTR2-A1_QFN56_7X7
YC1 = 32.768KHZ_12.5PF_9H03200042
YC2 = 24MHZ_10PF_8Y24000011
YL1 = 25MHZ_10PF_8Y25000010
YV1 = 27MHZ_16PF_X3G027000FG1H-HX
YVG1 = 25MHZ_10PF_7V25000014

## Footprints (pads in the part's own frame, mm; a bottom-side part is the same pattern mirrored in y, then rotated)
2N7002BKS_SOT363-6
  oval 0.508x0.559 smd: 1(-0.75,-0.9) 3(0.75,-0.9) 4(0.75,0.9) 6(-0.75,0.9)
  oval 0.406x0.61 smd: 2(0,-0.9) 5(0,0.9)
2N7002KDWH_SOT363-6
  oval 0.356x0.889 smd: 1(0,0) 2(0.65,0) 3(1.3,0) 4(1.3,1.6) 5(0.65,1.6) 6(0,1.6)
2N7002KW_SOT323-3
  oval 0.813x0.914 smd: 1(0,0) 2(0.65,1.6) 3(-0.65,1.6)
74AVCH2T45GD_XSON8_3X2
  oval 0.305x1.143 smd: 1(0,0.2)
  oval 0.305x1.041 smd: 2(0.5,0.149) 3(1,0.149) 4(1.5,0.149) 5(1.5,2.749) 6(1,2.749) 7(0.5,2.749) 8(0,2.749)
2160846033-A0_FCBGA_962P
  round 0.559 smd: A3(0.8,0) A37(26.8,0) A39(27.6,0) AU1(0,-26.8) AU3(0.8,-26.8) AU37(26.8,-26.8) AU39(27.6,-26.8) AW1(0,-27.6) AW3(0.8,-27.6) AW37(26.8,-27.6) AW39(27.6,-27.6) C1(0,-0.8) C3(0.8,-0.8) C37(26.8,-0.8) C39(27.6,-0.8)
  round 0.33 smd: A5(1.7,0) A35(25.9,0) AR1(0,-25.9) AR3(0.8,-25.9) AR5(1.7,-25.9) AR35(25.9,-25.9) AR37(26.8,-25.9) AR39(27.6,-25.9) AU5(1.7,-26.8) AU35(25.9,-26.8) AW5(1.7,-27.6) AW35(25.9,-27.6) C5(1.7,-0.8) C35(25.9,-0.8) E1(0,-1.7) E3(0.8,-1.7) E5(1.7,-1.7) E35(25.9,-1.7) E37(26.8,-1.7) E39(27.6,-1.7)
  round 0.406 smd: A6(2.6,0) A8(4.2,0) A10(5.8,0) A12(7.4,0) A14(9,0) A16(10.6,0) A18(12.2,0) A20(13.8,0) A22(15.4,0) A24(17,0) A26(18.6,0) A28(20.2,0) A30(21.8,0) A32(23.4,0) A34(25,0) AA2(0.4,-14.6) AA4(1.2,-14.6) AA6(2.4,-14.8) AA7(3.2,-15) AA8(4,-15) AA32(23.6,-15) AA33(24.4,-15) AA34(25.2,-14.8) AA36(26.4,-14.6) AA38(27.2,-14.6) AB1(0,-15.4) AB3(0.8,-15.4) AB5(1.6,-15.4) AB6(2.4,-15.6) AB34(25.2,-15.6) AB35(26,-15.4) AB37(26.8,-15.4) AB39(27.6,-15.4) AC2(0.4,-16.2) AC4(1.2,-16.2) AC6(2.4,-16.4) AC7(3.2,-16.2) AC8(4,-16.2) AC9(4.8,-16.2) AC31(22.8,-16.2) AC32(23.6,-16.2) AC33(24.4,-16.2) AC34(25.2,-16.4) AC36(26.4,-16.2) AC38(27.2,-16.2) AD1(0,-17) AD3(0.8,-17) AD5(1.6,-17) AD6(2.4,-17.2) AD7(3.2,-17.4) AD8(4,-17.4) AD9(4.8,-17.4) AD10(5.6,-17.4) AD30(22,-17.4) AD31(22.8,-17.4) AD32(23.6,-17.4) AD33(24.4,-17.4) AD34(25.2,-17.2) AD35(26,-17) AD37(26.8,-17) AD39(27.6,-17) AE2(0.4,-17.8) AE4(1.2,-17.8) AE6(2.4,-18) AE34(25.2,-18) AE36(26.4,-17.8) AE38(27.2,-17.8) AF1(0,-18.6) AF3(0.8,-18.6) AF5(1.6,-18.6) AF6(2.4,-18.8) AF7(3.2,-18.6) AF8(4,-18.6) AF9(4.8,-18.6) AF10(5.6,-18.6) AF11(6.4,-18.4) AF29(21.2,-18.6) AF30(22,-18.6) AF31(22.8,-18.6) AF32(23.6,-18.6) AF33(24.4,-18.6) AF34(25.2,-18.8) AF35(26,-18.6) AF37(26.8,-18.6) AF39(27.6,-18.6) AG2(0.4,-19.4) AG4(1.2,-19.4) AG6(2.4,-19.6) AG7(3.2,-19.8) AG8(4,-19.8) AG9(4.8,-19.8) AG10(5.6,-19.8) AG11(6.4,-19.4) AG12(7.4,-19.4) AG28(20.4,-19.4) AG29(21.2,-19.8) AG30(22,-19.8) AG31(22.8,-19.8) AG32(23.6,-19.8) AG33(24.4,-19.8) AG34(25.2,-19.6) AG36(26.4,-19.4) AG38(27.2,-19.4) AH1(0,-20.2) AH3(0.8,-20.2) AH5(1.6,-20.2) AH6(2.4,-20.4) AH11(6.4,-20.4) AH12(7.4,-20.4) AH28(20.4,-20.4) AH29(21.2,-20.6) AH34(25.2,-20.4) AH35(26,-20.2) AH37(26.8,-20.2) AH39(27.6,-20.2) AJ2(0.4,-21) AJ4(1.2,-21) AJ6(2.4,-21.2) AJ7(3.2,-21) AJ8(4,-21) AJ9(4.8,-21) AJ10(5.6,-21) AJ11(6.6,-21.2) AJ28(20.6,-21.2) AJ30(22,-21) AJ31(22.8,-21) AJ32(23.6,-21) AJ33(24.4,-21) AJ34(25.2,-21.2) AJ36(26.4,-21) AJ38(27.2,-21) AK1(0,-21.8) AK3(0.8,-21.8) AK5(1.6,-21.8) AK6(2.4,-22) AK7(3.2,-22) AK8(4,-22) AK9(4.8,-22) AK10(5.6,-22) AK11(6.6,-22) AK13(7.8,-22) AK14(9,-22) AK16(10.2,-22) AK24(17.4,-22) AK26(18.6,-22) AK27(19.8,-22) AK29(21,-22) AK30(22,-22) AK31(22.8,-22) AK32(23.6,-22) AK33(24.4,-22) AK34(25.2,-22) AK35(26,-21.8) AK37(26.8,-21.8) AK39(27.6,-21.8) AL2(0.4,-22.6) AL4(1.2,-22.6) AL6(2.4,-22.8) AL7(3.2,-22.8) AL8(4,-22.8) AL9(4.8,-22.8) AL10(5.6,-22.8) AL11(6.6,-22.8) AL13(7.8,-22.8) AL14(9,-22.8) AL16(10.2,-22.8) AL17(11.4,-22.8) AL23(16.2,-22.8) AL24(17.4,-22.8) AL26(18.6,-22.8) AL27(19.8,-22.8) AL29(21,-22.8) AL30(22,-22.8) AL31(22.8,-22.8) AL32(23.6,-22.8) AL33(24.4,-22.8) AL34(25.2,-22.8) AL36(26.4,-22.6) AL38(27.2,-22.6) AM1(0,-23.4) AM3(0.8,-23.4) AM5(1.6,-23.4) AM6(2.4,-23.6) AM7(3.2,-23.6) AM8(4,-23.6) AM9(4.8,-23.6) AM10(5.6,-23.6) AM11(6.6,-23.6) AM13(7.8,-23.6) AM14(9,-23.6) AM16(10.2,-23.6) AM17(11.4,-23.6) AM19(12.6,-23.6) AM21(15,-23.6) AM23(16.2,-23.6) AM24(17.4,-23.6) AM26(18.6,-23.6) AM27(19.8,-23.6) AM29(21,-23.6) AM30(22,-23.6) AM31(22.8,-23.6) AM32(23.6,-23.6) AM33(24.4,-23.6) AM34(25.2,-23.6) AM35(26,-23.4) AM37(26.8,-23.4) AM39(27.6,-23.4) AN2(0.4,-24.2) AN4(1.2,-24.2) AN6(2.4,-24.4) AN7(3.2,-24.4) AN8(4,-24.4) AN9(4.8,-24.4) AN10(5.6,-24.4) AN11(6.6,-24.4) AN13(7.8,-24.4) AN14(9,-24.4) AN16(10.2,-24.4) AN17(11.4,-24.4) AN19(12.6,-24.4) AN20(13.8,-24.4) AN21(15,-24.4) AN23(16.2,-24.4) AN24(17.4,-24.4) AN26(18.6,-24.4) AN27(19.8,-24.4) AN29(21,-24.4) AN30(22,-24.4) AN31(22.8,-24.4) AN32(23.6,-24.4) AN33(24.4,-24.4) AN34(25.2,-24.4) AN36(26.4,-24.2) AN38(27.2,-24.2) AP1(0,-25) AP3(0.8,-25) AP5(1.6,-25) AP6(2.4,-25.2) AP7(3.2,-25.2) AP8(4,-25.2) AP9(4.8,-25.2) AP10(5.6,-25.2) AP11(6.4,-25.2) AP12(7.2,-25.2) AP13(8,-25.2) AP14(8.8,-25.2) AP15(9.6,-25.2) AP16(10.4,-25.2) AP17(11.2,-25.2) AP18(12,-25.2) AP19(12.8,-25.2) AP20(13.8,-25.2) AP21(14.8,-25.2) AP22(15.6,-25.2) AP23(16.4,-25.2) AP24(17.2,-25.2) AP25(18,-25.2) AP26(18.8,-25.2) AP27(19.6,-25.2) AP28(20.4,-25.2) AP29(21.2,-25.2) AP30(22,-25.2) AP31(22.8,-25.2) AP32(23.6,-25.2) AP33(24.4,-25.2) AP34(25.2,-25.2) AP35(26,-25) AP37(26.8,-25) AP39(27.6,-25) AR6(2.6,-26) AR8(4.2,-26) AR10(5.8,-26) AR12(7.4,-26) AR14(9,-26) AR16(10.6,-26) AR18(12.2,-26) AR20(13.8,-26) AR22(15.4,-26) AR24(17,-26) AR26(18.6,-26) AR28(20.2,-26) AR30(21.8,-26) AR32(23.4,-26) AR34(25,-26) AT7(3.4,-26.4) AT9(5,-26.4) AT11(6.6,-26.4) AT13(8.2,-26.4) AT15(9.8,-26.4) AT17(11.4,-26.4) AT19(13,-26.4) AT21(14.6,-26.4) AT23(16.2,-26.4) AT25(17.8,-26.4) AT27(19.4,-26.4) AT29(21,-26.4) AT31(22.6,-26.4) AT33(24.2,-26.4) AU6(2.6,-26.8) AU8(4.2,-26.8) AU10(5.8,-26.8) AU12(7.4,-26.8) AU14(9,-26.8) AU16(10.6,-26.8) AU18(12.2,-26.8) AU20(13.8,-26.8) AU22(15.4,-26.8) AU24(17,-26.8) AU26(18.6,-26.8) AU28(20.2,-26.8) AU30(21.8,-26.8) AU32(23.4,-26.8) AU34(25,-26.8) AV7(3.4,-27.2) AV9(5,-27.2) AV11(6.6,-27.2) AV13(8.2,-27.2) AV15(9.8,-27.2) AV17(11.4,-27.2) AV19(13,-27.2) AV21(14.6,-27.2) AV23(16.2,-27.2) AV25(17.8,-27.2) AV27(19.4,-27.2) AV29(21,-27.2) AV31(22.6,-27.2) AV33(24.2,-27.2) AW6(2.6,-27.6) AW8(4.2,-27.6) AW10(5.8,-27.6) AW12(7.4,-27.6) AW14(9,-27.6) AW16(10.6,-27.6) AW18(12.2,-27.6) AW20(13.8,-27.6) AW22(15.4,-27.6) AW24(17,-27.6) AW26(18.6,-27.6) AW28(20.2,-27.6) AW30(21.8,-27.6) AW32(23.4,-27.6) AW34(25,-27.6) B7(3.4,-0.4) B9(5,-0.4) B11(6.6,-0.4) B13(8.2,-0.4) B15(9.8,-0.4) B17(11.4,-0.4) B19(13,-0.4) B21(14.6,-0.4) B23(16.2,-0.4) B25(17.8,-0.4) B27(19.4,-0.4) B29(21,-0.4) B31(22.6,-0.4) B33(24.2,-0.4) C6(2.6,-0.8) C8(4.2,-0.8) C10(5.8,-0.8) C12(7.4,-0.8) C14(9,-0.8) C16(10.6,-0.8) C18(12.2,-0.8) C20(13.8,-0.8) C22(15.4,-0.8) C24(17,-0.8) C26(18.6,-0.8) C28(20.2,-0.8) C30(21.8,-0.8) C32(23.4,-0.8) C34(25,-0.8) D7(3.4,-1.2) D9(5,-1.2) D11(6.6,-1.2) D13(8.2,-1.2) D15(9.8,-1.2) D17(11.4,-1.2) D19(13,-1.2) D21(14.6,-1.2) D23(16.2,-1.2) D25(17.8,-1.2) D27(19.4,-1.2) D29(21,-1.2) D31(22.6,-1.2) D33(24.2,-1.2) E6(2.6,-1.6) E8(4.2,-1.6) E10(5.8,-1.6) E12(7.4,-1.6) E14(9,-1.6) E16(10.6,-1.6) E18(12.2,-1.6) E20(13.8,-1.6) E22(15.4,-1.6) E24(17,-1.6) E26(18.6,-1.6) E28(20.2,-1.6) E30(21.8,-1.6) E32(23.4,-1.6) E34(25,-1.6) F1(0,-2.6) F3(0.8,-2.6) F5(1.6,-2.6) F6(2.4,-2.4) F7(3.2,-2.4) F8(4,-2.4) F9(4.8,-2.4) F10(5.6,-2.4) F11(6.4,-2.4) F12(7.2,-2.4) F13(8,-2.4) F14(8.8,-2.4) F15(9.6,-2.4) F16(10.4,-2.4) F17(11.2,-2.4) F18(12,-2.4) F19(12.8,-2.4) F20(13.8,-2.4) F21(14.8,-2.4) F22(15.6,-2.4) F23(16.4,-2.4) F24(17.2,-2.4) F25(18,-2.4) F26(18.8,-2.4) F27(19.6,-2.4) F28(20.4,-2.4) F29(21.2,-2.4) F30(22,-2.4) F31(22.8,-2.4) F32(23.6,-2.4) F33(24.4,-2.4) F34(25.2,-2.4) F35(26,-2.6) F37(26.8,-2.6) F39(27.6,-2.6) G2(0.4,-3.4) G4(1.2,-3.4) G6(2.4,-3.2) G7(3.2,-3.2) G8(4,-3.2) G9(4.8,-3.2) G10(5.6,-3.2) G11(6.6,-3.2) G13(7.8,-3.2) G14(9,-3.2) G16(10.2,-3.2) G17(11.4,-3.2) G19(12.6,-3.2) G20(13.8,-3.2) G21(15,-3.2) G23(16.2,-3.2) G24(17.4,-3.2) G26(18.6,-3.2) G27(19.8,-3.2) G29(21,-3.2) G30(22,-3.2) G31(22.8,-3.2) G32(23.6,-3.2) G33(24.4,-3.2) G34(25.2,-3.2) G36(26.4,-3.4) G38(27.2,-3.4) H1(0,-4.2) H3(0.8,-4.2) H5(1.6,-4.2) H6(2.4,-4) H7(3.2,-4) H8(4,-4) H9(4.8,-4) H10(5.6,-4) H11(6.6,-4) H13(7.8,-4) H14(9,-4) H16(10.2,-4) H17(11.4,-4) H19(12.6,-4) H21(15,-4) H23(16.2,-4) H24(17.4,-4) H26(18.6,-4) H27(19.8,-4) H29(21,-4) H30(22,-4) H31(22.8,-4) H32(23.6,-4) H33(24.4,-4) H34(25.2,-4) H35(26,-4.2) H37(26.8,-4.2) H39(27.6,-4.2) J2(0.4,-5) J4(1.2,-5) J6(2.4,-4.8) J7(3.2,-4.8) J8(4,-4.8) J9(4.8,-4.8) J10(5.6,-4.8) J11(6.6,-4.8) J13(7.8,-4.8) J14(9,-4.8) J16(10.2,-4.8) J17(11.4,-4.8) J23(16.2,-4.8) J24(17.4,-4.8) J26(18.6,-4.8) J27(19.8,-4.8) J29(21,-4.8) J30(22,-4.8) J31(22.8,-4.8) J32(23.6,-4.8) J33(24.4,-4.8) J34(25.2,-4.8) J36(26.4,-5) J38(27.2,-5) K1(0,-5.8) K3(0.8,-5.8) K5(1.6,-5.8) K6(2.4,-5.6) K7(3.2,-5.6) K8(4,-5.6) K9(4.8,-5.6) K10(5.6,-5.6) K11(6.6,-5.6) K13(7.8,-5.6) K14(9,-5.6) K16(10.2,-5.6) K24(17.4,-5.6) K26(18.6,-5.6) K27(19.8,-5.6) K29(21,-5.6) K30(22,-5.6) K31(22.8,-5.6) K32(23.6,-5.6) K33(24.4,-5.6) K34(25.2,-5.6) K35(26,-5.8) K37(26.8,-5.8) K39(27.6,-5.8) L2(0.4,-6.6) L4(1.2,-6.6) L6(2.4,-6.4) L7(3.2,-6.6) L8(4,-6.6) L9(4.8,-6.6) L10(5.6,-6.6) L11(6.4,-6.4) L12(7.4,-6.4) L28(20.4,-6.4) L29(21.2,-6.6) L30(22,-6.6) L31(22.8,-6.6) L32(23.6,-6.6) L33(24.4,-6.6) L34(25.2,-6.4) L36(26.4,-6.6) L38(27.2,-6.6) M1(0,-7.4) M3(0.8,-7.4) M5(1.6,-7.4) M6(2.4,-7.2) M11(6.4,-7.4) M12(7.4,-7.4) M28(20.4,-7.4) M34(25.2,-7.2) M35(26,-7.4) M37(26.8,-7.4) M39(27.6,-7.4) N2(0.4,-8.2) N4(1.2,-8.2) N6(2.4,-8) N7(3.2,-7.8) N8(4,-7.8) N9(4.8,-7.8) N10(5.6,-7.8) N11(6.4,-8.4) N12(7.4,-8.4) N28(20.4,-8.4) N29(21.2,-7.8) N30(22,-7.8) N31(22.8,-7.8) N32(23.6,-7.8) N33(24.4,-7.8) N34(25.2,-8) N36(26.4,-8.2) N38(27.2,-8.2) P1(0,-9) P3(0.8,-9) P5(1.6,-9) P6(2.4,-8.8) P7(3.2,-9) P8(4,-9) P9(4.8,-9) P10(5.6,-9) P29(21.2,-9) P30(22,-9) P31(22.8,-9) P32(23.6,-9) P33(24.4,-9) P34(25.2,-8.8) P35(26,-9) P37(26.8,-9) P39(27.6,-9) R2(0.4,-9.8) R4(1.2,-9.8) R6(2.4,-9.6) R11(6.4,-9.4) R34(25.2,-9.6) R36(26.4,-9.8) R38(27.2,-9.8) T1(0,-10.6) T3(0.8,-10.6) T5(1.6,-10.6) T6(2.4,-10.4) T7(3.2,-10.2) T8(4,-10.2) T9(4.8,-10.2) T10(5.6,-10.2) T30(22,-10.2) T31(22.8,-10.2) T32(23.6,-10.2) T33(24.4,-10.2) T34(25.2,-10.4) T35(26,-10.6) T37(26.8,-10.6) T39(27.6,-10.6) U2(0.4,-11.4) U4(1.2,-11.4) U6(2.4,-11.2) U7(3.2,-11.4) U8(4,-11.4) U9(4.8,-11.4) U31(22.8,-11.4) U32(23.6,-11.4) U33(24.4,-11.4) U34(25.2,-11.2) U36(26.4,-11.4) U38(27.2,-11.4) V1(0,-12.2) V3(0.8,-12.2) V5(1.6,-12.2) V6(2.4,-12) V34(25.2,-12) V35(26,-12.2) V37(26.8,-12.2) V39(27.6,-12.2) W2(0.4,-13) W4(1.2,-13) W6(2.4,-12.8) W7(3.2,-12.6) W8(4,-12.6) W32(23.6,-12.6) W33(24.4,-12.6) W34(25.2,-12.8) W36(26.4,-13) W38(27.2,-13) Y1(0,-13.8) Y3(0.8,-13.8) Y5(1.6,-13.8) Y6(2.4,-13.8) Y7(3.2,-13.8) Y33(24.4,-13.8) Y34(25.2,-13.8) Y35(26,-13.8) Y37(26.8,-13.8) Y39(27.6,-13.8)
  round 0.508 smd: AA9(4.8,-15) AA10(5.6,-15) AA11(6.4,-14.4) AA12(7.4,-14.4) AA13(8.4,-14.4) AA15(9.4,-14.4) AA16(10.4,-14.4) AA17(11.4,-14.4) AA18(12.4,-14.4) AA20(13.4,-14.4) AA21(14.4,-14.4) AA22(15.4,-14.4) AA23(16.4,-14.4) AA24(17.4,-14.4) AA26(18.4,-14.4) AA27(19.4,-14.4) AA28(20.4,-14.4) AA29(21.2,-15) AA30(22,-15) AA31(22.8,-15) AB11(6.4,-15.4) AB12(7.4,-15.4) AB13(8.4,-15.4) AB15(9.4,-15.4) AB16(10.4,-15.4) AB17(11.4,-15.4) AB18(12.4,-15.4) AB20(13.4,-15.4) AB21(14.4,-15.4) AB22(15.4,-15.4) AB23(16.4,-15.4) AB24(17.4,-15.4) AB26(18.4,-15.4) AB27(19.4,-15.4) AB28(20.4,-15.4) AC10(5.6,-16.2) AC11(6.4,-16.4) AC12(7.4,-16.4) AC13(8.4,-16.4) AC15(9.4,-16.4) AC16(10.4,-16.4) AC17(11.4,-16.4) AC18(12.4,-16.4) AC20(13.4,-16.4) AC21(14.4,-16.4) AC22(15.4,-16.4) AC23(16.4,-16.4) AC24(17.4,-16.4) AC26(18.4,-16.4) AC27(19.4,-16.4) AC28(20.4,-16.4) AC29(21.2,-16.2) AC30(22,-16.2) AD11(6.4,-17.4) AD12(7.4,-17.4) AD13(8.4,-17.4) AD15(9.4,-17.4) AD16(10.4,-17.4) AD17(11.4,-17.4) AD18(12.4,-17.4) AD20(13.4,-17.4) AD21(14.4,-17.4) AD22(15.4,-17.4) AD23(16.4,-17.4) AD24(17.4,-17.4) AD26(18.4,-17.4) AD27(19.4,-17.4) AD28(20.4,-17.4) AD29(21.2,-17.4) AF12(7.4,-18.4) AF13(8.4,-18.4) AF15(9.4,-18.4) AF16(10.4,-18.4) AF17(11.4,-18.4) AF18(12.4,-18.4) AF20(13.4,-18.4) AF21(14.4,-18.4) AF22(15.4,-18.4) AF23(16.4,-18.4) AF24(17.4,-18.4) AF26(18.4,-18.4) AF27(19.4,-18.4) AF28(20.4,-18.4) AG13(8.4,-19.4) AG15(9.4,-19.4) AG16(10.4,-19.4) AG17(11.4,-19.4) AG18(12.4,-19.4) AG20(13.4,-19.4) AG21(14.4,-19.4) AG22(15.4,-19.4) AG23(16.4,-19.4) AG24(17.4,-19.4) AG26(18.4,-19.4) AG27(19.4,-19.4) AH13(8.4,-20.4) AH15(9.4,-20.4) AH16(10.4,-20.4) AH17(11.4,-20.4) AH18(12.4,-20.4) AH20(13.4,-20.4) AH21(14.4,-20.4) AH22(15.4,-20.4) AH23(16.4,-20.4) AH24(17.4,-20.4) AH26(18.4,-20.4) AH27(19.4,-20.4) AJ13(7.8,-21.2) AJ14(9,-21.2) AJ16(10.2,-21.2) AJ17(11.4,-21.2) AJ19(12.6,-21.2) AJ20(13.8,-21.2) AJ21(15,-21.2) AJ23(16.2,-21.2) AJ24(17.4,-21.2) AJ26(18.6,-21.2) AJ27(19.8,-21.2) AK17(11.4,-22) AK19(12.6,-22) AK20(13.8,-22) AK21(15,-22) AK23(16.2,-22) AL19(12.6,-22.8) AL20(13.8,-22.8) AL21(15,-22.8) AM20(13.8,-23.6) H20(13.8,-4) J19(12.6,-4.8) J20(13.8,-4.8) J21(15,-4.8) K17(11.4,-5.6) K19(12.6,-5.6) K20(13.8,-5.6) K21(15,-5.6) K23(16.2,-5.6) L13(8.4,-6.4) L15(9.4,-6.4) L16(10.4,-6.4) L17(11.4,-6.4) L18(12.4,-6.4) L20(13.4,-6.4) L21(14.4,-6.4) L22(15.4,-6.4) L23(16.4,-6.4) L24(17.4,-6.4) L26(18.4,-6.4) L27(19.4,-6.4) M13(8.4,-7.4) M15(9.4,-7.4) M16(10.4,-7.4) M17(11.4,-7.4) M18(12.4,-7.4) M20(13.4,-7.4) M21(14.4,-7.4) M22(15.4,-7.4) M23(16.4,-7.4) M24(17.4,-7.4) M26(18.4,-7.4) M27(19.4,-7.4) N13(8.4,-8.4) N15(9.4,-8.4) N16(10.4,-8.4) N17(11.4,-8.4) N18(12.4,-8.4) N20(13.4,-8.4) N21(14.4,-8.4) N22(15.4,-8.4) N23(16.4,-8.4) N24(17.4,-8.4) N26(18.4,-8.4) N27(19.4,-8.4) R12(7.4,-9.4) R13(8.4,-9.4) R15(9.4,-9.4) R16(10.4,-9.4) R17(11.4,-9.4) R18(12.4,-9.4) R20(13.4,-9.4) R21(14.4,-9.4) R22(15.4,-9.4) R23(16.4,-9.4) R24(17.4,-9.4) R26(18.4,-9.4) R27(19.4,-9.4) R28(20.4,-9.4) T11(6.4,-10.4) T12(7.4,-10.4) T13(8.4,-10.4) T15(9.4,-10.4) T16(10.4,-10.4) T17(11.4,-10.4) T18(12.4,-10.4) T20(13.4,-10.4) T21(14.4,-10.4) T22(15.4,-10.4) T23(16.4,-10.4) T24(17.4,-10.4) T26(18.4,-10.4) T27(19.4,-10.4) T28(20.4,-10.4) T29(21.2,-10.2) U10(5.6,-11.4) U11(6.4,-11.4) U12(7.4,-11.4) U13(8.4,-11.4) U15(9.4,-11.4) U16(10.4,-11.4) U17(11.4,-11.4) U18(12.4,-11.4) U20(13.4,-11.4) U21(14.4,-11.4) U22(15.4,-11.4) U23(16.4,-11.4) U24(17.4,-11.4) U26(18.4,-11.4) U27(19.4,-11.4) U28(20.4,-11.4) U29(21.2,-11.4) U30(22,-11.4) V11(6.4,-12.4) V12(7.4,-12.4) V13(8.4,-12.4) V15(9.4,-12.4) V16(10.4,-12.4) V17(11.4,-12.4) V18(12.4,-12.4) V20(13.4,-12.4) V21(14.4,-12.4) V22(15.4,-12.4) V23(16.4,-12.4) V24(17.4,-12.4) V26(18.4,-12.4) V27(19.4,-12.4) V28(20.4,-12.4) W9(4.8,-12.6) W10(5.6,-12.6) W29(21.2,-12.6) W30(22,-12.6) W31(22.8,-12.6) Y8(4,-13.8) Y9(4.8,-13.8) Y10(5.6,-13.8) Y11(6.4,-13.4) Y12(7.4,-13.4) Y13(8.4,-13.4) Y15(9.4,-13.4) Y16(10.4,-13.4) Y17(11.4,-13.4) Y18(12.4,-13.4) Y20(13.4,-13.4) Y21(14.4,-13.4) Y22(15.4,-13.4) Y23(16.4,-13.4) Y24(17.4,-13.4) Y26(18.4,-13.4) Y27(19.4,-13.4) Y28(20.4,-13.4) Y29(21.2,-13.8) Y30(22,-13.8) Y31(22.8,-13.8) Y32(23.6,-13.8)
ACES_50271-00701-001_7P-T
  oval 0.787x1.6 smd: 1(0,0) 2(-1.25,0) 3(-2.5,0) 4(-3.75,0) 5(-5,0) 6(-6.25,0) 7(-7.5,0)
  rect 2.108x2.997 smd: 8(2.55,2.9) 9(-10.05,2.9)
ACES_50406-02071-001_20P
  oval 0.254x1.295 smd: 1(0,0) 2(0.5,0) 3(1,0) 4(1.5,0) 5(2,0) 6(2.5,0) 7(3,0) 8(3.5,0) 9(4,0) 10(4.5,0) 11(5,0) 12(5.5,0) 13(6,0) 14(6.5,0) 15(7,0) 16(7.5,0) 17(8,0) 18(8.5,0) 19(9,0) 20(9.5,0)
  rect 1.194x2.692 smd: 21(-2.4,1.95) 22(11.9,1.95)
  rect 2.311x1.295 smd: 23(0.85,3.9) 24(8.65,3.9)
ACES_50463-0104A-P01_10P-T
  oval 0.203x1.194 smd: 1(0,0) 2(-0.4,0) 3(-0.8,0) 4(-1.2,0) 5(-1.6,0) 6(-2,0) 7(-2.4,0) 8(-2.8,0) 9(-3.2,0) 10(-3.6,0)
  rect 1.397x2.007 smd: 11(2.5,1.37) 12(-6.1,1.37)
ACES_50506-01201-001_12P-T
  oval 0.305x0.889 smd: 1(0,0) 2(-0.5,0) 3(-1,0) 4(-1.5,0) 5(-2,0) 6(-2.5,0) 7(-3,0) 8(-3.5,0) 9(-4,0) 10(-4.5,0) 11(-5,0) 12(-5.5,0)
  rect 0.991x2.007 smd: 13(2.1,3.05) 14(-7.6,3.05)
ACES_50506-01201-AT1_12P
  oval 0.406x0.991 smd: 1(0,0) 2(-0.5,0) 3(-1,0) 4(-1.5,0) 5(-2,0) 6(-2.5,0) 7(-3,0) 8(-3.5,0) 9(-4,0) 10(-4.5,0) 11(-5,0) 12(-5.5,0)
  rect 0.991x2.007 smd: 13(2.1,3.05) 14(-7.6,3.05)
ACES_50812-0227P-001_22P-T
  round 1.194 hole 1.194 unplated: (-38.86,-1.58) (9.14,-1.58)
  oval 0.889x2.388 smd: 1(0,0) 2(-1.27,0) 3(-2.54,0) 4(-3.81,0) 5(-5.08,0) 6(-6.35,0) 7(-7.62,0) 8(-13.97,0) 9(-15.24,0) 10(-16.51,0) 11(-17.78,0) 12(-19.05,0) 13(-20.32,0) 14(-21.59,0) 15(-22.86,0) 16(-24.13,0) 17(-25.4,0) 18(-26.67,0) 19(-27.94,0) 20(-29.21,0) 21(-30.48,0) 22(-31.75,0)
  round 5.994 hole 2.311: 23(11.14,-2.58) 24(-40.86,-2.58)
ACES_50885-0137P-001_13P-T
  round 1.194 hole 1.194 unplated: (-19.78,-1.75) (1.02,-1.75)
  round 0.991 hole 0.711: 1(0,0) 2(-1.27,0) 3(-2.54,0) 4(-3.81,0) 5(-5.08,0) 6(-6.35,0) 7(-7.62,0)
  round 0.991 hole 0.61: 8(-13.83,1) 9(-14.83,0) 10(-15.83,1) 11(-16.83,0) 12(-17.83,1) 13(-18.83,0)
  custom 1.162x1.162 hole 2.311: 14(-22.53,-0.75) 15(3.77,-0.75)
ACES_85205-05001_5P-T
  oval 0.787x1.6 smd: 1(0,0) 2(1.25,0) 3(2.5,0) 4(3.75,0) 5(5,0)
  rect 2.108x2.997 smd: 6(-2.55,2.9) 7(7.55,2.9)
ACES_88514-0060N-071_6P-T
  oval 0.61x1.295 smd: 1(0,0) 2(-1,0) 3(-2,0) 4(-3,0) 5(-4,0) 6(-5,0)
  rect 2.159x2.21 smd: 7(2.825,3.05) 8(-7.825,3.05)
ACES_91960-0084N_8P
  oval 0.889x1.346 smd: 1(0,0) 2(-1.27,0) 3(-2.54,0) 4(-3.81,0) 5(-3.81,-7.35) 6(-2.54,-7.35) 7(-1.27,-7.35) 8(0,-7.35)
AO3401A_SOT23-3
  oval 1.016x1.524 smd: 1(0,0) 2(0.965,2.083) 3(-0.965,2.083)
AO3413_SOT23-3
  oval 1.016x1.524 smd: 1(0,0) 2(0.965,2.083) 3(-0.965,2.083)
AO4430L_SO8
  oval 0.635x1.854 smd: 1(0,0) 2(1.27,0) 3(2.54,0) 4(3.81,0) 5(3.81,5.165) 6(2.54,5.165) 7(1.27,5.165) 8(0,5.165)
AZ5425-01F_DFN1006P2E2
  rect 0.559x0.61 smd: 1(0,0) 2(0.85,0)
AZC199-02SPR7G_SOT23-3
  oval 1.016x1.524 smd: 1(0,0) 2(0.965,2.083) 3(-0.965,2.083)
BAT54CW_SOT323-3
  oval 0.66x0.864 smd: 1(0,0) 2(-0.65,-1.85) 3(0.65,-1.85)
BQ24780RUYR_QFN24_4X4
  oval 0.305x0.889 smd: 1(0,0) 2(0.4,0) 3(0.8,0) 4(1.2,0) 5(1.6,0) 6(2,0) 7(2.4,0) 15(2.4,4) 16(2,4) 17(1.6,4) 18(1.2,4) 19(0.8,4) 20(0.4,4) 21(0,4)
  oval 0.889x0.305 smd: 8(3.2,0.8) 9(3.2,1.2) 10(3.2,1.6) 11(3.2,2) 12(3.2,2.4) 13(3.2,2.8) 14(3.2,3.2) 22(-0.8,3.2) 23(-0.8,2.8) 24(-0.8,2.4) 25(-0.8,2) 26(-0.8,1.6) 27(-0.8,1.2) 28(-0.8,0.8)
  rect 2.591x2.591 smd: 29(1.2,2)
